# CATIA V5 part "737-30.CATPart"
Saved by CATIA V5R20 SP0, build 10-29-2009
Part number: 737-30
Definition: NONE
Nomenclature: 737-30
Source: Unknown
Description: 737-30
Bounding box of the stored display mesh (mm): x -36 to 28, y -35.911 to 35.911, z -47 to 25
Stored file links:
  C:\Users\Utente\Desktop\IO LAVORO\3D X SITO CF\X SITO\737\737-30.CATPart
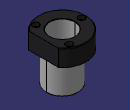
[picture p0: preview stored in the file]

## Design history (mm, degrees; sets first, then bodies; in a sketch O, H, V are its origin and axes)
Body1 "737-30" (main body)
  Solid1: solid without history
